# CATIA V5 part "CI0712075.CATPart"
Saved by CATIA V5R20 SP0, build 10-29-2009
Part number: CI0712075
Bounding box of the stored display mesh (mm): x -12 to 12, y -10.279 to 93, z -11.988 to 14.27
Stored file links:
  C:\Users\Raffaele\Desktop\3D X SITO CF\BOLEX\19-INCLINED ASSEMBLY REF_CI\CI0712075.CATPart
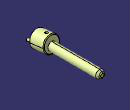
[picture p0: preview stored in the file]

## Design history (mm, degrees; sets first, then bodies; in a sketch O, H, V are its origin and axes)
Set1
  DatumSurface1 to DatumSurface16 "MANIFOLD_SOLID_BREP #379"
  DatumSurface17 to DatumSurface39 "MANIFOLD_SOLID_BREP #1096"
Body1 (main body)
